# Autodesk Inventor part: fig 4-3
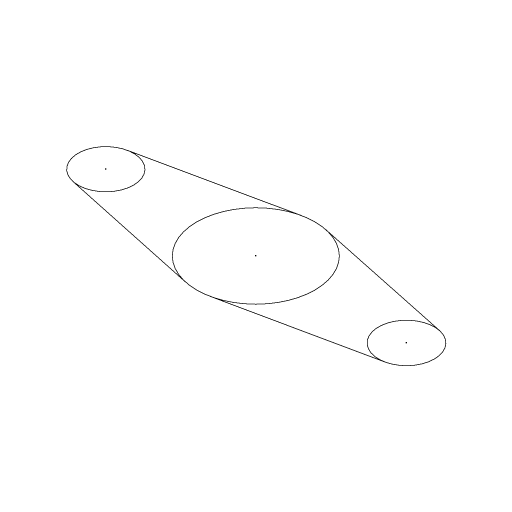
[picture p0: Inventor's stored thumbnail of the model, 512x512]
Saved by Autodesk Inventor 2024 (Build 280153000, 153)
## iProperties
Created: 2005-02
Part Number: fig 4-3
Document SubType Name: Modeling
Designer: CADCIM
Manufacturer: Standard
Standards Organization: Custom
Density: 1 g/cm^3
Material: Generic
Appearance: Default
Author: CADCIM
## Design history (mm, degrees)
sketch "Sketch1"
  geometry: L1 (-33.874, 5.844)-(-2.722, 12.469); L2 (2.595, 12.472)-(33.871, 5.852); L3 (-33.884, -5.902)-(-2.745, -12.585); L4 (2.595, -12.592)-(33.871, -5.972); A1 r 12.81 centre (-0.057, -0.06) between (-2.722, 12.469) and (2.595, 12.472); A2 r 6.006 centre (-32.624, -0.03) between (-33.874, 5.844) and (-33.884, -5.902); A3 r 6.043 centre (32.619, -0.06) between (33.871, 5.852) and (33.871, -5.972)
  constraints: 8 end point, 8 point on circle, 8 tangent, 3 centre point, 1 other
